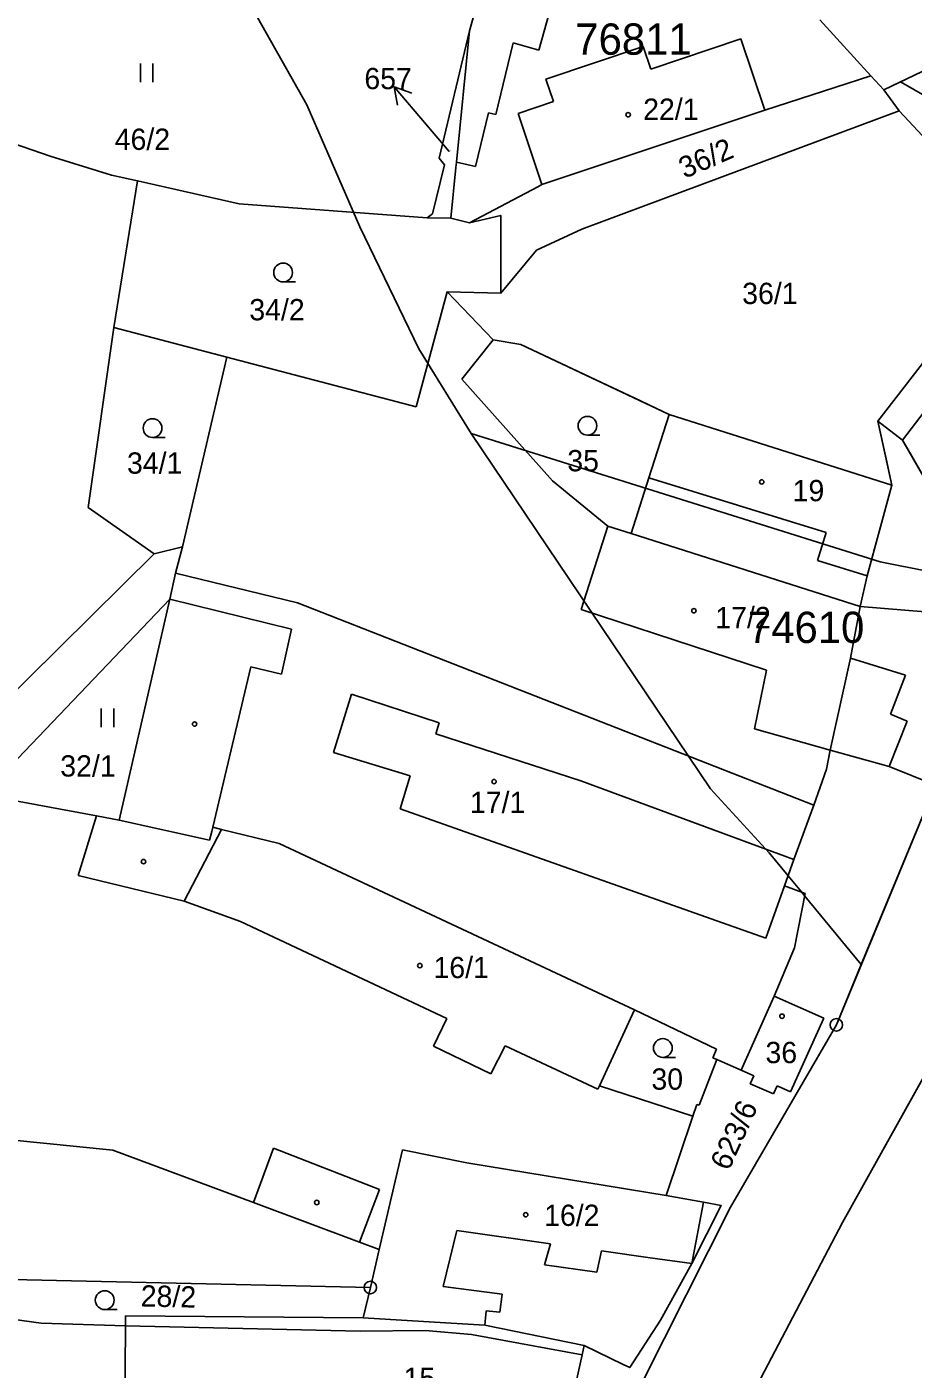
# Model space of a CAD drawing. Extents: x -743888 to -742027, y -1128394 to -1126768.
# Drawn here: x -742956.8 to -742886, y -1127432.2 to -1127325 of the extents above; entities that cross this region are included whole.
import ezdxf

# ---------------------------------------------------------------- set-up
doc = ezdxf.new("R2010")
doc.units = 0
for name, color, linetype in [('Vrstva 1', 7, 'Continuous'), ('Vrstva 16', 7, 'Continuous'), ('Vrstva 18', 7, 'Continuous'), ('Vrstva 19', 7, 'Continuous'), ('Vrstva 24', 7, 'Continuous'), ('Vrstva 25', 7, 'Continuous'), ('Vrstva 3', 7, 'Continuous'), ('Vrstva 37', 7, 'Continuous'), ('Vrstva 4', 7, 'Continuous'), ('Vrstva 52', 7, 'Continuous'), ('Vrstva 53', 7, 'Continuous'), ('Vrstva 6', 7, 'Continuous')]:
    doc.layers.add(name, color=color, linetype=linetype)

msp = doc.modelspace()

# ---------------------------------------------------------------- linework, layer by layer
at = {"layer": 'Vrstva 1'}
for p, q in [((-742926.8, -1127414.71), (-742928.65, -1127422.67)), ((-742928.65, -1127422.67), (-742929.36, -1127425.71)), ((-742966.36, -1127424.88), (-742929.36, -1127425.71)), ((-742929.36, -1127425.71), (-742929.93, -1127428.12))]:
    msp.add_line(p, q, dxfattribs=at)
for points in [[(-742921.45, -1127325.33), (-742918.89, -1127316.24)], [(-742893.46, -1127324.46), (-742889.39, -1127328.94)], [(-742923.87, -1127335.5), (-742921.45, -1127325.33)], [(-742897.86, -1127331.69), (-742889.39, -1127328.94)], [(-742889.39, -1127328.94), (-742888.34, -1127330.05)], [(-742971.84, -1127329.53), (-742954.93, -1127335.36)], [(-742913.83, -1127337.01), (-742897.86, -1127331.69)], [(-742912.48, -1127341.19), (-742887.13, -1127331.73)], [(-742887.13, -1127331.73), (-742877.76, -1127341.76)], [(-742954.93, -1127335.36), (-742950.04, -1127336.87)], [(-742924.39, -1127339.95), (-742923.44, -1127336.04)], [(-742923.87, -1127335.5), (-742923.44, -1127336.04)], [(-742950.04, -1127336.87), (-742947.95, -1127337.31)], [(-742949.84, -1127349.03), (-742947.95, -1127337.31)], [(-742947.95, -1127337.31), (-742939.84, -1127339.16)], [(-742915.66, -1127337.62), (-742913.83, -1127337.01)], [(-742939.84, -1127339.16), (-742924.83, -1127340.27)], [(-742924.83, -1127340.27), (-742924.39, -1127339.95)], [(-742922.93, -1127340.3), (-742921.43, -1127340.67)], [(-742916.08, -1127342.87), (-742912.48, -1127341.19)], [(-742918.93, -1127346.28), (-742916.08, -1127342.87)], [(-742925.69, -1127355.37), (-742923.23, -1127346.19)], [(-742923.23, -1127346.19), (-742918.93, -1127346.28)], [(-742949.84, -1127349.03), (-742940.83, -1127351.4)], [(-742922.06, -1127353.17), (-742919.55, -1127350.01)], [(-742919.55, -1127350.01), (-742917.35, -1127350.39)], [(-742917.35, -1127350.39), (-742905.5, -1127355.98)], [(-742888.82, -1127356.51), (-742883.97, -1127350.26)], [(-742944.36, -1127366.56), (-742940.83, -1127351.4)], [(-742940.83, -1127351.4), (-742925.69, -1127355.37)], [(-742922.06, -1127353.17), (-742914.82, -1127361.29)], [(-742907.12, -1127361.05), (-742905.5, -1127355.98)], [(-742905.5, -1127355.98), (-742887.7, -1127361.63)], [(-742888.82, -1127356.51), (-742886.85, -1127358.03)], [(-742888.82, -1127356.51), (-742887.7, -1127361.63)], [(-742886.85, -1127358.03), (-742882.34, -1127365.88)], [(-742908.53, -1127365.48), (-742907.12, -1127361.05)], [(-742914.82, -1127361.29), (-742910.38, -1127364.89)], [(-742889.69, -1127368.86), (-742887.7, -1127361.63)], [(-742910.38, -1127364.89), (-742908.53, -1127365.48)], [(-742908.53, -1127365.48), (-742890.23, -1127371.33)], [(-742964.3, -1127384.57), (-742946.62, -1127367.12)], [(-742944.92, -1127368.65), (-742944.36, -1127366.56)], [(-742945.39, -1127370.73), (-742944.92, -1127368.65)], [(-742890.23, -1127371.33), (-742889.69, -1127368.86)], [(-742960.31, -1127386.35), (-742945.39, -1127370.73)], [(-742949.42, -1127388.37), (-742945.39, -1127370.73)], [(-742891.01, -1127375.44), (-742890.23, -1127371.33)], [(-742890.23, -1127371.33), (-742883.09, -1127371.9)], [(-742892.63, -1127382.79), (-742891.01, -1127375.44)], [(-742892.92, -1127384.32), (-742892.63, -1127382.79)], [(-742892.63, -1127382.79), (-742887.91, -1127384.11)], [(-742893.95, -1127387.18), (-742892.92, -1127384.32)], [(-742887.91, -1127384.11), (-742884.23, -1127385.59)], [(-742960.31, -1127386.35), (-742951.24, -1127388.03)], [(-742895.53, -1127391.52), (-742893.95, -1127387.18)], [(-742951.24, -1127388.03), (-742949.42, -1127388.37)], [(-742949.42, -1127388.37), (-742942.2, -1127389.97)], [(-742942.03, -1127389.28), (-742941.95, -1127388.95)], [(-742941.95, -1127388.95), (-742941.26, -1127389.12)], [(-742942.2, -1127389.97), (-742942.03, -1127389.28)], [(-742941.26, -1127389.12), (-742936.65, -1127390.26)], [(-742936.65, -1127390.26), (-742908.27, -1127403.53)], [(-742896.28, -1127393.64), (-742895.53, -1127391.52)], [(-742891.64, -1127420.53), (-742877.58, -1127395.3)], [(-742897.1, -1127402.44), (-742895.48, -1127398.58)], [(-742899.75, -1127408.35), (-742897.1, -1127402.44)], [(-742897.1, -1127402.44), (-742893.13, -1127404.2)], [(-742911.06, -1127409.61), (-742908.27, -1127403.53)], [(-742908.27, -1127403.53), (-742901.71, -1127406.68)], [(-742900.6, -1127419.3), (-742892.14, -1127404.73)], [(-742895.81, -1127410.07), (-742893.13, -1127404.2)], [(-742902.01, -1127407.37), (-742901.71, -1127406.68)], [(-742903.09, -1127411.14), (-742901.69, -1127407.51)], [(-742902.01, -1127407.37), (-742901.69, -1127407.51)], [(-742901.69, -1127407.51), (-742899.75, -1127408.35)], [(-742899.75, -1127408.35), (-742898.74, -1127408.79)], [(-742899.02, -1127409.44), (-742898.74, -1127408.79)], [(-742911.06, -1127409.61), (-742903.6, -1127412.02)], [(-742899.02, -1127409.44), (-742897.15, -1127410.25)], [(-742897.15, -1127410.25), (-742896.87, -1127409.6)], [(-742896.87, -1127409.6), (-742895.81, -1127410.07)], [(-742903.6, -1127412.02), (-742903.28, -1127411.08)], [(-742903.28, -1127411.08), (-742903.09, -1127411.14)], [(-742975.01, -1127412.21), (-742949.94, -1127414.75)], [(-742905.74, -1127418.36), (-742903.6, -1127412.02)], [(-742926.8, -1127414.71), (-742921.65, -1127415.74)], [(-742949.94, -1127414.75), (-742938.69, -1127418.93)], [(-742921.65, -1127415.74), (-742905.74, -1127418.36)], [(-742938.69, -1127418.93), (-742930.23, -1127422.08)], [(-742905.74, -1127418.36), (-742902.75, -1127418.9)], [(-742902.75, -1127418.9), (-742901.33, -1127419.16), (-742903.67, -1127423.8)], [(-742907.65, -1127433.29), (-742900.6, -1127419.3)], [(-742902.44, -1127441.06), (-742891.64, -1127420.53)], [(-742930.23, -1127422.08), (-742928.65, -1127422.67)], [(-742903.67, -1127423.8), (-742906.18, -1127428.31), (-742908.64, -1127432.1), (-742909.18, -1127431.85)], [(-742962.06, -1127427.67), (-742955.66, -1127428.57)], [(-742955.66, -1127428.57), (-742948.92, -1127428.77)], [(-742948.92, -1127428.77), (-742948.91, -1127427.98)], [(-742948.91, -1127427.98), (-742929.93, -1127428.12)], [(-742929.93, -1127428.12), (-742924.25, -1127428.47)], [(-742924.25, -1127428.47), (-742920.21, -1127428.73)], [(-742920.21, -1127428.73), (-742912.29, -1127430.35)], [(-742912.45, -1127431.08), (-742912.29, -1127430.35)], [(-742912.29, -1127430.35), (-742909.18, -1127431.85)], [(-742913.85, -1127437.46), (-742912.45, -1127431.08)]]:
    msp.add_lwpolyline(points, dxfattribs=at)
at = {"layer": 'Vrstva 16'}
msp.add_line((-742927.19, -1127331.29), (-742927.46, -1127329.81), dxfattribs=at)
for points in [[(-742924.87, -1127332.86), (-742927.46, -1127329.81), (-742926.05, -1127330.32)], [(-742923.06, -1127334.99), (-742924.87, -1127332.86)]]:
    msp.add_lwpolyline(points, dxfattribs=at)
at = {"layer": 'Vrstva 24'}
for p, q in [((-742892.19, -1127404.73), (-742892.09, -1127404.73)), ((-742929.41, -1127425.71), (-742929.31, -1127425.71))]:
    msp.add_line(p, q, dxfattribs=at)
for centre in [(-742892.14, -1127404.73), (-742929.36, -1127425.71)]:
    msp.add_circle(centre, 0.499, dxfattribs=at)
at = {"layer": 'Vrstva 25'}
for p, q in [((-742947.73, -1127327.95), (-742947.73, -1127329.45)), ((-742946.73, -1127329.45), (-742946.73, -1127327.95)), ((-742936.33, -1127345.39), (-742935.33, -1127345.39)), ((-742946.76, -1127357.82), (-742945.76, -1127357.82)), ((-742912.02, -1127357.63), (-742911.02, -1127357.63)), ((-742950.85, -1127379.46), (-742950.85, -1127380.96)), ((-742949.85, -1127380.96), (-742949.85, -1127379.46)), ((-742906, -1127407.33), (-742905, -1127407.33)), ((-742950.58, -1127427.47), (-742949.58, -1127427.47))]:
    msp.add_line(p, q, dxfattribs=at)
for centre, radius in [((-742908.77, -1127332.04), 0.175), ((-742936.33, -1127344.64), 0.75), ((-742946.76, -1127357.07), 0.75), ((-742912.02, -1127356.88), 0.75), ((-742898.1, -1127361.37), 0.175), ((-742903.52, -1127371.66), 0.175), ((-742943.4, -1127380.71), 0.175), ((-742919.48, -1127385.3), 0.175), ((-742947.48, -1127391.69), 0.175), ((-742925.41, -1127400), 0.175), ((-742896.48, -1127404.04), 0.175), ((-742906, -1127406.58), 0.75), ((-742933.64, -1127418.92), 0.175), ((-742916.95, -1127419.9), 0.175), ((-742950.58, -1127426.72), 0.75)]:
    msp.add_circle(centre, radius, dxfattribs=at)
at = {"layer": 'Vrstva 3'}
for points in [[(-742915.34, -1127329.19), (-742907.57, -1127326.6)], [(-742907.57, -1127326.6), (-742906.97, -1127328.4)], [(-742906.97, -1127328.4), (-742899.76, -1127325.99)], [(-742899.76, -1127325.99), (-742897.86, -1127331.69)], [(-742915.34, -1127329.19), (-742914.74, -1127330.99)], [(-742917.56, -1127331.93), (-742914.74, -1127330.99)], [(-742917.56, -1127331.93), (-742915.66, -1127337.62)], [(-742913.83, -1127337.01), (-742897.86, -1127331.69)], [(-742915.66, -1127337.62), (-742913.83, -1127337.01)], [(-742907.12, -1127361.05), (-742905.5, -1127355.98)], [(-742905.5, -1127355.98), (-742887.7, -1127361.63)], [(-742907.12, -1127361.05), (-742892.95, -1127365.42)], [(-742889.69, -1127368.86), (-742887.7, -1127361.63)], [(-742912.51, -1127371.57), (-742910.38, -1127364.89)], [(-742910.38, -1127364.89), (-742908.53, -1127365.48)], [(-742908.53, -1127365.48), (-742890.23, -1127371.33)], [(-742893.64, -1127367.64), (-742892.95, -1127365.42)], [(-742893.64, -1127367.64), (-742889.69, -1127368.86)], [(-742912.51, -1127371.57), (-742897.71, -1127376.41)], [(-742891.01, -1127375.44), (-742890.23, -1127371.33)], [(-742891.01, -1127375.44), (-742890.23, -1127371.33)], [(-742890.23, -1127371.33), (-742883.09, -1127371.9)], [(-742892.63, -1127382.79), (-742891.01, -1127375.44)], [(-742891.01, -1127375.44), (-742886.61, -1127376.79)], [(-742898.67, -1127381.09), (-742897.71, -1127376.41)], [(-742887.82, -1127379.92), (-742886.61, -1127376.79)], [(-742932.31, -1127382.97), (-742930.88, -1127378.32)], [(-742930.88, -1127378.32), (-742923.86, -1127380.6)], [(-742887.82, -1127379.92), (-742886.47, -1127380.48)], [(-742924.14, -1127381.49), (-742923.86, -1127380.6)], [(-742898.67, -1127381.09), (-742892.63, -1127382.79)], [(-742887.91, -1127384.11), (-742886.47, -1127380.48)], [(-742924.14, -1127381.49), (-742912.56, -1127385.25)], [(-742932.31, -1127382.97), (-742926.18, -1127384.84)], [(-742887.91, -1127384.11), (-742884.23, -1127385.59)], [(-742926.99, -1127387.48), (-742926.18, -1127384.84)], [(-742912.56, -1127385.25), (-742895.53, -1127391.52)], [(-742926.99, -1127387.48), (-742897.76, -1127397.8)], [(-742944.23, -1127394.84), (-742941.26, -1127389.12)], [(-742941.26, -1127389.12), (-742936.65, -1127390.26)], [(-742936.65, -1127390.26), (-742908.27, -1127403.53)], [(-742896.28, -1127393.64), (-742895.53, -1127391.52)], [(-742897.76, -1127397.8), (-742896.28, -1127393.64)], [(-742944.23, -1127394.84), (-742939.73, -1127396.48)], [(-742939.73, -1127396.48), (-742923.25, -1127404.22)], [(-742899.75, -1127408.35), (-742897.1, -1127402.44)], [(-742897.1, -1127402.44), (-742893.13, -1127404.2)], [(-742911.06, -1127409.61), (-742908.27, -1127403.53)], [(-742924.31, -1127406.44), (-742923.25, -1127404.22)], [(-742895.81, -1127410.07), (-742893.13, -1127404.2)], [(-742924.31, -1127406.44), (-742919.73, -1127408.63)], [(-742919.73, -1127408.63), (-742918.58, -1127406.41)], [(-742918.58, -1127406.41), (-742911.19, -1127409.88)], [(-742899.75, -1127408.35), (-742898.74, -1127408.79)], [(-742899.02, -1127409.44), (-742898.74, -1127408.79)], [(-742911.19, -1127409.88), (-742911.06, -1127409.61)], [(-742899.02, -1127409.44), (-742897.15, -1127410.25)], [(-742897.15, -1127410.25), (-742896.87, -1127409.6)], [(-742896.87, -1127409.6), (-742895.81, -1127410.07)], [(-742926.8, -1127414.71), (-742928.65, -1127422.67)], [(-742926.8, -1127414.71), (-742921.65, -1127415.74)], [(-742921.65, -1127415.74), (-742905.74, -1127418.36)], [(-742905.74, -1127418.36), (-742902.75, -1127418.9)], [(-742903.67, -1127423.8), (-742902.75, -1127418.9)], [(-742923.55, -1127425.62), (-742922.46, -1127421.16)], [(-742922.46, -1127421.16), (-742914.96, -1127422.21)], [(-742915.46, -1127423.9), (-742914.96, -1127422.21)], [(-742928.65, -1127422.67), (-742929.36, -1127425.71)], [(-742911.26, -1127424.49), (-742910.91, -1127422.78)], [(-742910.91, -1127422.78), (-742907.01, -1127423.33)], [(-742915.46, -1127423.9), (-742911.26, -1127424.49)], [(-742907.01, -1127423.33), (-742903.67, -1127423.8)], [(-742929.36, -1127425.71), (-742929.93, -1127428.12)], [(-742923.55, -1127425.62), (-742918.84, -1127426.23)], [(-742919.02, -1127427.67), (-742918.84, -1127426.23)], [(-742920.21, -1127428.73), (-742920.12, -1127427.56)], [(-742920.12, -1127427.56), (-742919.02, -1127427.67)], [(-742929.93, -1127428.12), (-742924.25, -1127428.47)], [(-742924.25, -1127428.47), (-742920.21, -1127428.73)], [(-742948.97, -1127435.6), (-742948.92, -1127428.77)], [(-742948.92, -1127428.77), (-742930.18, -1127429.19)], [(-742930.18, -1127429.19), (-742924.99, -1127429.13)], [(-742924.99, -1127429.13), (-742921.28, -1127429.47)], [(-742921.28, -1127429.47), (-742912.45, -1127431.08)], [(-742913.85, -1127437.46), (-742912.45, -1127431.08)]]:
    msp.add_lwpolyline(points, dxfattribs=at)
at = {"layer": 'Vrstva 37'}
for centre in [(-742908.77, -1127332.04), (-742898.1, -1127361.37), (-742903.52, -1127371.66), (-742919.48, -1127385.3), (-742925.41, -1127400), (-742896.48, -1127404.04), (-742916.95, -1127419.9)]:
    msp.add_circle(centre, 0.175, dxfattribs=at)
at = {"layer": 'Vrstva 4'}
for points in [[(-742915.91, -1127326.89), (-742912.87, -1127316.06)], [(-742919.35, -1127332.03), (-742917.96, -1127326.31)], [(-742917.96, -1127326.31), (-742915.91, -1127326.89)], [(-742915.34, -1127329.19), (-742907.57, -1127326.6)], [(-742907.57, -1127326.6), (-742906.97, -1127328.4)], [(-742906.97, -1127328.4), (-742899.76, -1127325.99)], [(-742899.76, -1127325.99), (-742897.86, -1127331.69)], [(-742915.34, -1127329.19), (-742914.74, -1127330.99)], [(-742917.56, -1127331.93), (-742914.74, -1127330.99)], [(-742920.95, -1127336.18), (-742919.93, -1127331.9)], [(-742919.93, -1127331.9), (-742919.35, -1127332.03)], [(-742917.56, -1127331.93), (-742915.66, -1127337.62)], [(-742922.49, -1127335.83), (-742920.95, -1127336.18)], [(-742886.85, -1127358.03), (-742881.92, -1127351.58)], [(-742907.12, -1127361.05), (-742892.95, -1127365.42)], [(-742912.51, -1127371.57), (-742910.38, -1127364.89)], [(-742893.64, -1127367.64), (-742892.95, -1127365.42)], [(-742893.64, -1127367.64), (-742889.69, -1127368.86)], [(-742945.39, -1127370.73), (-742935.66, -1127373.12)], [(-742912.51, -1127371.57), (-742897.71, -1127376.41)], [(-742936.47, -1127376.72), (-742935.66, -1127373.12)], [(-742891.01, -1127375.44), (-742886.61, -1127376.79)], [(-742941.95, -1127388.95), (-742938.92, -1127376.14)], [(-742938.92, -1127376.14), (-742936.47, -1127376.72)], [(-742898.67, -1127381.09), (-742897.71, -1127376.41)], [(-742887.82, -1127379.92), (-742886.61, -1127376.79)], [(-742932.31, -1127382.97), (-742930.88, -1127378.32)], [(-742930.88, -1127378.32), (-742923.86, -1127380.6)], [(-742887.82, -1127379.92), (-742886.47, -1127380.48)], [(-742924.14, -1127381.49), (-742923.86, -1127380.6)], [(-742898.67, -1127381.09), (-742892.63, -1127382.79)], [(-742887.91, -1127384.11), (-742886.47, -1127380.48)], [(-742924.14, -1127381.49), (-742912.56, -1127385.25)], [(-742932.31, -1127382.97), (-742926.18, -1127384.84)], [(-742926.99, -1127387.48), (-742926.18, -1127384.84)], [(-742912.56, -1127385.25), (-742895.53, -1127391.52)], [(-742926.99, -1127387.48), (-742897.76, -1127397.8)], [(-742952.69, -1127392.81), (-742951.24, -1127388.03)], [(-742944.23, -1127394.84), (-742941.26, -1127389.12)], [(-742952.69, -1127392.81), (-742944.23, -1127394.84)], [(-742897.76, -1127397.8), (-742896.28, -1127393.64)], [(-742944.23, -1127394.84), (-742939.73, -1127396.48)], [(-742939.73, -1127396.48), (-742923.25, -1127404.22)], [(-742924.31, -1127406.44), (-742923.25, -1127404.22)], [(-742924.31, -1127406.44), (-742919.73, -1127408.63)], [(-742919.73, -1127408.63), (-742918.58, -1127406.41)], [(-742918.58, -1127406.41), (-742911.19, -1127409.88)], [(-742911.19, -1127409.88), (-742911.06, -1127409.61)], [(-742938.69, -1127418.93), (-742937.11, -1127414.59)], [(-742937.11, -1127414.59), (-742928.64, -1127417.89)], [(-742930.23, -1127422.08), (-742928.64, -1127417.89)], [(-742903.67, -1127423.8), (-742902.75, -1127418.9)], [(-742923.55, -1127425.62), (-742922.46, -1127421.16)], [(-742922.46, -1127421.16), (-742914.96, -1127422.21)], [(-742915.46, -1127423.9), (-742914.96, -1127422.21)], [(-742911.26, -1127424.49), (-742910.91, -1127422.78)], [(-742910.91, -1127422.78), (-742907.01, -1127423.33)], [(-742915.46, -1127423.9), (-742911.26, -1127424.49)], [(-742907.01, -1127423.33), (-742903.67, -1127423.8)], [(-742923.55, -1127425.62), (-742918.84, -1127426.23)], [(-742919.02, -1127427.67), (-742918.84, -1127426.23)], [(-742920.21, -1127428.73), (-742920.12, -1127427.56)], [(-742920.12, -1127427.56), (-742919.02, -1127427.67)], [(-742948.97, -1127435.6), (-742948.92, -1127428.77)], [(-742948.92, -1127428.77), (-742930.18, -1127429.19)], [(-742930.18, -1127429.19), (-742924.99, -1127429.13)], [(-742924.99, -1127429.13), (-742921.28, -1127429.47)], [(-742921.28, -1127429.47), (-742912.45, -1127431.08)]]:
    msp.add_lwpolyline(points, dxfattribs=at)
at = {"layer": 'Vrstva 52'}
for points in [[(-742960.63, -1127292.88), (-742941.63, -1127318.5), (-742934.44, -1127331.25), (-742930.19, -1127341), (-742925.5, -1127350.75), (-742921.31, -1127357.5)], [(-742882.34, -1127365.88), (-742886.51, -1127358.62), (-742886.85, -1127358.03), (-742888.82, -1127356.51), (-742888.16, -1127359.53), (-742887.7, -1127361.63), (-742905.5, -1127355.98), (-742907.73, -1127354.93), (-742917.35, -1127350.39), (-742919.55, -1127350.01), (-742923.23, -1127346.19), (-742918.93, -1127346.28), (-742918.95, -1127340.08), (-742921.43, -1127340.67), (-742915.99, -1127337.79), (-742915.66, -1127337.62), (-742913.83, -1127337.01), (-742897.86, -1127331.69), (-742889.39, -1127328.94), (-742888.34, -1127330.05), (-742887.02, -1127329.42), (-742881, -1127332.88)], [(-742921.31, -1127357.5), (-742888.63, -1127367.75), (-742876.7, -1127370.12)], [(-742921.31, -1127357.5), (-742902.19, -1127385.88), (-742897.5, -1127391), (-742895.99, -1127392.83), (-742894.93, -1127394.12), (-742894.67, -1127394.44), (-742890.15, -1127399.92)], [(-742890.15, -1127399.92), (-742884.23, -1127385.59), (-742882.85, -1127386.15), (-742878.02, -1127373.93), (-742876.7, -1127370.12)], [(-742972.89, -1127572.54), (-742971.19, -1127569.17), (-742967.51, -1127562.65), (-742960.97, -1127550.69), (-742958.07, -1127544.59), (-742952.01, -1127529.96), (-742951.87, -1127529.63), (-742949.93, -1127524.86), (-742947.48, -1127518.45), (-742943.52, -1127507.49), (-742939.27, -1127495.28), (-742928.77, -1127471.57), (-742930.03, -1127470.75), (-742926.01, -1127462.54), (-742919.56, -1127450.77), (-742911.88, -1127437.64), (-742907.65, -1127433.29), (-742900.6, -1127419.3), (-742892.14, -1127404.73), (-742890.15, -1127399.92)], [(-742965.26, -1127573.48), (-742964.75, -1127572.6), (-742958.43, -1127564.08), (-742954.72, -1127554.49), (-742950.97, -1127547.61), (-742944.28, -1127528.98), (-742929.86, -1127490.53), (-742926.08, -1127481.57), (-742925.07, -1127479.17), (-742918.99, -1127466.07), (-742914.39, -1127456.16), (-742910.36, -1127448.54), (-742907.43, -1127444.81), (-742902.44, -1127441.06), (-742891.64, -1127420.53), (-742883.68, -1127406.25)]]:
    msp.add_lwpolyline(points, dxfattribs=at)
at = {"layer": 'Vrstva 6'}
for points in [[(-742922.49, -1127335.83), (-742921.45, -1127325.33)], [(-742888.34, -1127330.05), (-742879.78, -1127325.96)], [(-742888.34, -1127330.05), (-742887.13, -1127331.73)], [(-742922.93, -1127340.3), (-742922.53, -1127336.26)], [(-742922.53, -1127336.26), (-742922.49, -1127335.83)], [(-742921.43, -1127340.67), (-742915.99, -1127337.79)], [(-742915.99, -1127337.79), (-742915.66, -1127337.62)], [(-742924.83, -1127340.27), (-742922.93, -1127340.3)], [(-742921.43, -1127340.67), (-742918.95, -1127340.08)], [(-742918.95, -1127340.08), (-742918.93, -1127346.28)], [(-742923.23, -1127346.19), (-742919.55, -1127350.01)], [(-742951.91, -1127363.4), (-742949.84, -1127349.03)], [(-742951.91, -1127363.4), (-742946.62, -1127367.12)], [(-742946.62, -1127367.12), (-742944.36, -1127366.56)], [(-742944.92, -1127368.65), (-742935.19, -1127371.02)], [(-742935.19, -1127371.02), (-742893.95, -1127387.18)], [(-742892.14, -1127404.73), (-742884.23, -1127385.59)], [(-742896.28, -1127393.64), (-742894.63, -1127394.23)], [(-742895.48, -1127398.58), (-742894.63, -1127394.23)]]:
    msp.add_lwpolyline(points, dxfattribs=at)

# ---------------------------------------------------------------- texts
at = {"layer": 'Vrstva 16'}
msp.add_text('657', height=1.7, dxfattribs=at).set_placement((-742929.84, -1127330))
at = {"layer": 'Vrstva 18'}
for s, height, p in [('46/2', 1.7, (-742949.78, -1127334.85)), ('657', 0.1, (-742923.17, -1127334.99)), ('36/1', 1.7, (-742899.66, -1127347.16)), ('34/2', 1.7, (-742939.03, -1127348.46)), ('34/1', 1.7, (-742948.8, -1127360.71)), ('35', 1.7, (-742913.63, -1127360.52)), ('32/1', 1.7, (-742954.13, -1127384.9)), ('30', 1.7, (-742906.91, -1127409.91))]:
    msp.add_text(s, height=height, dxfattribs=at).set_placement(p)
for s, rotation, p in [('36/2', 23.5523, (-742904.26, -1127337.17)), ('623/6', 65.5948, (-742900.73, -1127416.46)), ('28/2', 358.7149, (-742947.72, -1127427.22))]:
    msp.add_text(s, height=1.7, rotation=rotation, dxfattribs=at).set_placement(p)
at = {"layer": 'Vrstva 19'}
for s, p in [('22/1', (-742907.57, -1127332.45)), ('19', (-742895.63, -1127362.91)), ('17/2', (-742901.81, -1127373.05)), ('17/1', (-742921.41, -1127387.82)), ('16/1', (-742924.32, -1127401)), ('36', (-742897.8, -1127407.79)), ('16/2', (-742915.48, -1127420.79)), ('15', (-742926.71, -1127433.8))]:
    msp.add_text(s, height=1.7, dxfattribs=at).set_placement(p)
at = {"layer": 'Vrstva 53'}
for s, p in [('76811', (-742912.99, -1127327.25)), ('74610', (-742899.2, -1127374.23))]:
    msp.add_text(s, height=2.5, dxfattribs=at).set_placement(p)

doc.saveas('drawing.dxf')
